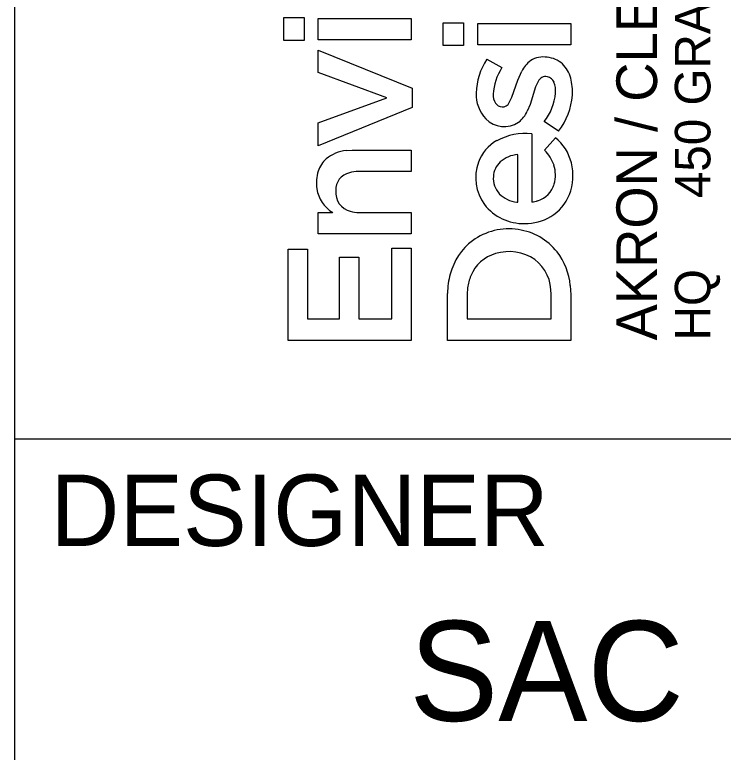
# Model space of a CAD drawing. Extents: x 0 to 34, y 0 to 22.
# Drawn here: x 32 to 32.993, y 2.061 to 3.094 of the extents above; entities that cross this region are included whole.
import ezdxf

# ---------------------------------------------------------------- set-up
doc = ezdxf.new("R2010")
doc.units = 0
doc.layers.add('SH_Border', color=7, linetype='Continuous')
doc.layers.add('SH_Data', color=7, linetype='Continuous')

msp = doc.modelspace()

# ---------------------------------------------------------------- linework, layer by layer
at = {"layer": 'SH_Border'}
for p, q in [((32, 0.5), (32, 21.5)), ((32, 2.5), (33.5, 2.5))]:
    msp.add_line(p, q, dxfattribs=at)
at = {"layer": 'SH_Data'}
for p, q in [((32.3771, 3.0582), (32.3771, 3.0903)), ((32.3771, 3.0903), (32.4054, 3.0903)), ((32.4054, 3.0903), (32.4054, 3.0582)), ((32.4254, 3.0594), (32.4254, 3.0893)), ((32.4254, 3.0893), (32.5557, 3.0893)), ((32.5557, 3.0893), (32.5557, 3.0594)), ((32.6005, 3.0511), (32.6005, 3.0832)), ((32.6005, 3.0832), (32.6289, 3.0832)), ((32.6289, 3.0832), (32.6289, 3.0511)), ((32.6489, 3.0523), (32.6489, 3.0822)), ((32.6489, 3.0822), (32.7792, 3.0822)), ((32.7792, 3.0822), (32.7792, 3.0523)), ((32.5557, 3.0594), (32.4254, 3.0594)), ((32.4054, 3.0582), (32.3771, 3.0582)), ((32.6289, 3.0511), (32.6005, 3.0511)), ((32.7792, 3.0523), (32.6489, 3.0523)), ((32.4254, 3.0133), (32.4254, 3.0446)), ((32.4254, 3.0446), (32.5567, 2.9913)), ((32.6615, 3.0321), (32.6827, 3.0203)), ((32.5212, 2.978), (32.4254, 3.0133)), ((32.7048, 3.0026), (32.7104, 3.0153)), ((32.6967, 2.9787), (32.7048, 3.0026)), ((32.7334, 3.001), (32.7298, 2.9933)), ((32.5567, 2.9913), (32.5567, 2.9644)), ((32.7298, 2.9933), (32.7221, 2.9688)), ((32.4254, 2.9429), (32.5212, 2.978)), ((32.693, 2.9712), (32.6967, 2.9787)), ((32.7221, 2.9688), (32.7182, 2.9592)), ((32.5567, 2.9644), (32.4254, 2.9109)), ((32.4254, 2.9109), (32.4254, 2.9429)), ((32.7621, 2.9314), (32.742, 2.9447)), ((32.7245, 2.9275), (32.7246, 2.8319)), ((32.7423, 2.9046), (32.7577, 2.922)), ((32.4644, 2.904), (32.4729, 2.9044)), ((32.4729, 2.9044), (32.5557, 2.9044)), ((32.5557, 2.9044), (32.5557, 2.8746)), ((32.7049, 2.8318), (32.7049, 2.8983)), ((32.5557, 2.8746), (32.4814, 2.8746)), ((32.7036, 2.8317), (32.7049, 2.8318)), ((32.4254, 2.7875), (32.4254, 2.8173)), ((32.4254, 2.8173), (32.4455, 2.8173)), ((32.4822, 2.8173), (32.5557, 2.8173)), ((32.5557, 2.8173), (32.5557, 2.7876)), ((32.5557, 2.7876), (32.4254, 2.7875)), ((32.383, 2.6379), (32.383, 2.766)), ((32.383, 2.766), (32.4101, 2.766)), ((32.4101, 2.766), (32.4101, 2.6683)), ((32.5286, 2.6683), (32.5286, 2.7672)), ((32.5286, 2.7672), (32.5557, 2.7672)), ((32.5557, 2.7672), (32.5557, 2.6379)), ((32.455, 2.6683), (32.455, 2.7549)), ((32.455, 2.7549), (32.4822, 2.7549)), ((32.4822, 2.7549), (32.4822, 2.6683)), ((32.6347, 2.7118), (32.6341, 2.7023)), ((32.7785, 2.715), (32.7792, 2.7021)), ((32.6064, 2.638), (32.6064, 2.704)), ((32.6341, 2.7023), (32.6341, 2.6684)), ((32.7515, 2.6683), (32.7515, 2.7024)), ((32.7792, 2.7021), (32.7792, 2.638)), ((32.4101, 2.6683), (32.455, 2.6683)), ((32.4822, 2.6683), (32.5286, 2.6683)), ((32.6341, 2.6684), (32.7515, 2.6683)), ((32.5557, 2.6379), (32.383, 2.6379)), ((32.7792, 2.638), (32.6064, 2.638))]:
    msp.add_line(p, q, dxfattribs=at)
for points in [[(32.3771, 3.0582), (32.3771, 3.0903), (32.4054, 3.0903), (32.4054, 3.0582)], [(32.4254, 3.0594), (32.4254, 3.0893), (32.5557, 3.0893), (32.5557, 3.0594)], [(32.6005, 3.0511), (32.6005, 3.0832), (32.6289, 3.0832), (32.6289, 3.0511)], [(32.6489, 3.0523), (32.6489, 3.0822), (32.7792, 3.0822), (32.7792, 3.0523)], [(32.4254, 2.9109), (32.4254, 2.9429), (32.5212, 2.978), (32.4254, 3.0133), (32.4254, 3.0446), (32.5567, 2.9913), (32.5567, 2.9644)], [(32.383, 2.6379), (32.383, 2.766), (32.4101, 2.766), (32.4101, 2.6683), (32.455, 2.6683), (32.455, 2.7549), (32.4822, 2.7549), (32.4822, 2.6683), (32.5286, 2.6683), (32.5286, 2.7672), (32.5557, 2.7672), (32.5557, 2.6379)]]:
    msp.add_lwpolyline(points, close=True, dxfattribs=at)
for points in [[(32.6615, 3.0321), (32.6827, 3.0203)], [(32.693, 2.9712), (32.6967, 2.9787), (32.7048, 3.0026), (32.7104, 3.0153)], [(32.7334, 3.001), (32.7298, 2.9933), (32.7221, 2.9688), (32.7182, 2.9592)], [(32.7621, 2.9314), (32.742, 2.9447)], [(32.7245, 2.9275), (32.7246, 2.8319)], [(32.7423, 2.9046), (32.7577, 2.922)], [(32.4644, 2.904), (32.4729, 2.9044), (32.5557, 2.9044), (32.5557, 2.8746), (32.4814, 2.8746)], [(32.7036, 2.8317), (32.7049, 2.8318), (32.7049, 2.8983)], [(32.4254, 2.7875), (32.4254, 2.8173), (32.4455, 2.8173)], [(32.4822, 2.8173), (32.5557, 2.8173), (32.5557, 2.7876), (32.4254, 2.7875)], [(32.7785, 2.715), (32.7792, 2.7021), (32.7792, 2.638), (32.6064, 2.638)], [(32.6347, 2.7118), (32.6341, 2.7023), (32.6341, 2.6684), (32.7515, 2.6683), (32.7515, 2.7024)], [(32.6064, 2.638), (32.6064, 2.704)]]:
    msp.add_lwpolyline(points, dxfattribs=at)
for centre, radius, start, end in [((32.7364, 2.9826), 0.0897, 146.531, 178.7571), ((32.7364, 2.9826), 0.0897, 146.531, 178.7571), ((32.7466, 2.9971), 0.0405, 125.5118, 153.4159), ((32.7466, 2.9971), 0.0405, 125.5118, 153.4159), ((32.7406, 3.0026), 0.0326, 80.1719, 122.5197), ((32.7406, 3.0026), 0.0326, 80.1719, 122.5197), ((32.7428, 2.9982), 0.0367, 47.7934, 84.6892), ((32.7428, 2.9982), 0.0367, 47.7934, 84.6892), ((32.7452, 2.9789), 0.0749, 146.5112, 176.9101), ((32.7452, 2.9789), 0.0749, 146.5112, 176.9101), ((32.7379, 2.9946), 0.0427, 14.9966, 46.2063), ((32.7379, 2.9946), 0.0427, 14.9966, 46.2063), ((32.7438, 2.9963), 0.0114, 76.6609, 155.7053), ((32.7438, 2.9963), 0.0114, 76.6609, 155.7053), ((32.744, 2.9951), 0.0126, 21.5098, 78.5262), ((32.744, 2.9951), 0.0126, 21.5098, 78.5262), ((32.7259, 2.9877), 0.0321, 354.5726, 22.068), ((32.7259, 2.9877), 0.0321, 354.5726, 22.068), ((32.7104, 2.9867), 0.0712, 355.8306, 15.3914), ((32.7104, 2.9867), 0.0712, 355.8306, 15.3914), ((32.6967, 2.9824), 0.0501, 177.5366, 222.7932), ((32.6967, 2.9824), 0.0501, 177.5366, 222.7932), ((32.6931, 2.9823), 0.0228, 178.4747, 211.0868), ((32.6931, 2.9823), 0.0228, 178.4747, 211.0868), ((32.6825, 2.9915), 0.0757, 321.811, 354.7969), ((32.6825, 2.9915), 0.0757, 321.811, 354.7969), ((32.6895, 2.9882), 0.0922, 321.9777, 355.8738), ((32.6895, 2.9882), 0.0922, 321.9777, 355.8738), ((32.6833, 2.9767), 0.0115, 212.2368, 268.3777), ((32.6833, 2.9767), 0.0115, 212.2368, 268.3777), ((32.6834, 2.9759), 0.0107, 267.716, 333.7337), ((32.6834, 2.9759), 0.0107, 267.716, 333.7337), ((32.681, 2.9758), 0.0408, 308.0877, 335.9874), ((32.681, 2.9758), 0.0408, 308.0877, 335.9874), ((32.686, 2.9753), 0.0375, 225.9854, 302.4797), ((32.686, 2.9753), 0.0375, 225.9854, 302.4797), ((32.7152, 2.8441), 0.0838, 83.615, 118.2876), ((32.7152, 2.8441), 0.0838, 83.615, 118.2876), ((32.7024, 2.8691), 0.0558, 118.8308, 160.6244), ((32.7024, 2.8691), 0.0558, 118.8308, 160.6244), ((32.7174, 2.8717), 0.0644, 13.5336, 51.3615), ((32.7174, 2.8717), 0.0644, 13.5336, 51.3615), ((32.4687, 2.8543), 0.0499, 94.9696, 130.2225), ((32.4687, 2.8543), 0.0499, 94.9696, 130.2225), ((32.7038, 2.8656), 0.0549, 19.0357, 45.4406), ((32.7038, 2.8656), 0.0549, 19.0357, 45.4406), ((32.7079, 2.8561), 0.0424, 94.008, 130.8817), ((32.7079, 2.8561), 0.0424, 94.008, 130.8817), ((32.4635, 2.8626), 0.0402, 132.2219, 161.6818), ((32.4635, 2.8626), 0.0402, 132.2219, 161.6818), ((32.7104, 2.8661), 0.0644, 160.5201, 215.7831), ((32.7104, 2.8661), 0.0644, 160.5201, 215.7831), ((32.7005, 2.8663), 0.0298, 132.9851, 177.179), ((32.7005, 2.8663), 0.0298, 132.9851, 177.179), ((32.7107, 2.8697), 0.047, 344.6059, 17.007), ((32.7107, 2.8697), 0.047, 344.6059, 17.007), ((32.7064, 2.8692), 0.0758, 339.3542, 13.3785), ((32.7064, 2.8692), 0.0758, 339.3542, 13.3785), ((32.4787, 2.8582), 0.056, 162.2736, 187.7919), ((32.4787, 2.8582), 0.056, 162.2736, 187.7919), ((32.4748, 2.8487), 0.025, 103.6865, 182.2187), ((32.4748, 2.8487), 0.025, 103.6865, 182.2187), ((32.4811, 2.8286), 0.046, 89.6049, 105.3284), ((32.4811, 2.8286), 0.046, 89.6049, 105.3284), ((32.7017, 2.865), 0.0311, 175.0013, 223.283), ((32.7017, 2.865), 0.0311, 175.0013, 223.283), ((32.7224, 2.8671), 0.035, 288.0077, 343.5508), ((32.7224, 2.8671), 0.035, 288.0077, 343.5508), ((32.4703, 2.858), 0.0476, 188.962, 238.7037), ((32.4703, 2.858), 0.0476, 188.962, 238.7037), ((32.4773, 2.8456), 0.0276, 175.5854, 255.1439), ((32.4773, 2.8456), 0.0276, 175.5854, 255.1439), ((32.7089, 2.8736), 0.0423, 225.0619, 262.7974), ((32.7089, 2.8736), 0.0423, 225.0619, 262.7974), ((32.7189, 2.8652), 0.0626, 300.9427, 338.7323), ((32.7189, 2.8652), 0.0626, 300.9427, 338.7323), ((32.7247, 2.8522), 0.0202, 269.7003, 294.8711), ((32.7247, 2.8522), 0.0202, 269.7003, 294.8711), ((32.7125, 2.8705), 0.0687, 217.7452, 271.6543), ((32.7125, 2.8705), 0.0687, 217.7452, 271.6543), ((32.4818, 2.8595), 0.0422, 254.0916, 270.5284), ((32.4818, 2.8595), 0.0422, 254.0916, 270.5284), ((32.7155, 2.8724), 0.0706, 269.2048, 300.3341), ((32.7155, 2.8724), 0.0706, 269.2048, 300.3341), ((32.6923, 2.7079), 0.0864, 81.194, 125.9984), ((32.6923, 2.7079), 0.0864, 81.194, 125.9984), ((32.6946, 2.7113), 0.0827, 37.8521, 82.402), ((32.6946, 2.7113), 0.0827, 37.8521, 82.402), ((32.6939, 2.7089), 0.0865, 127.2362, 165.148), ((32.6939, 2.7089), 0.0865, 127.2362, 165.148), ((32.6889, 2.7078), 0.054, 106.1881, 157.3861), ((32.6889, 2.7078), 0.054, 106.1881, 157.3861), ((32.6928, 2.6986), 0.0639, 55.6727, 107.2093), ((32.6928, 2.6986), 0.0639, 55.6727, 107.2093), ((32.6859, 2.7057), 0.0931, 5.7333, 37.304), ((32.6859, 2.7057), 0.0931, 5.7333, 37.304), ((32.6929, 2.705), 0.0587, 357.4662, 52.2665), ((32.6929, 2.705), 0.0587, 357.4662, 52.2665), ((32.7143, 2.7028), 0.1078, 164.7861, 179.3704), ((32.7143, 2.7028), 0.1078, 164.7861, 179.3704), ((32.6983, 2.7039), 0.0641, 157.3571, 172.9275), ((32.6983, 2.7039), 0.0641, 157.3571, 172.9275)]:
    msp.add_arc(centre, radius, start, end, dxfattribs=at)

# ---------------------------------------------------------------- texts
for s, height, p in [('450 GRANT ST., AKRON, OH  44311', 0.049846, (32.9749, 2.8374)), ('AKRON / CLEVELAND / COLUMBUS', 0.056969, (32.9001, 2.638)), ('HQ ', 0.04985, (32.9749, 2.638))]:
    msp.add_text(s, height=height, rotation=90, dxfattribs=at).set_placement(p)
for s, height, p in [('DESIGNER', 0.1, (32.05, 2.35)), ('SAC', 0.14, (32.5528, 2.105))]:
    msp.add_text(s, height=height, dxfattribs=at).set_placement(p)

doc.saveas('drawing.dxf')
